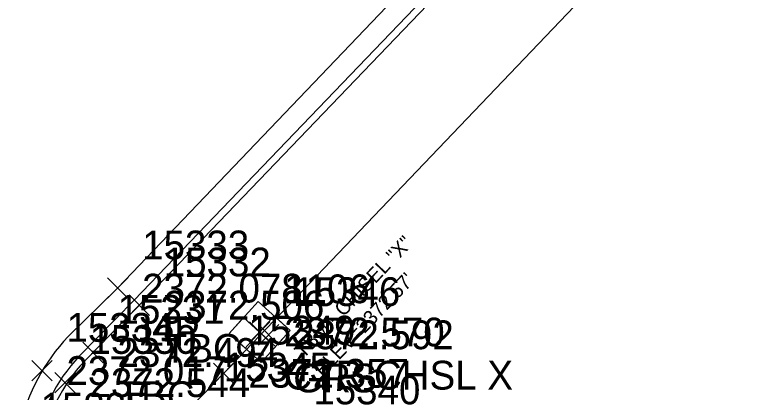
# Model space of a CAD drawing. Extents: x 2377639 to 2379738, y 729875 to 732734.
# Drawn here: x 2378647.8 to 2378700, y 730820.1 to 730846.3 of the extents above; entities that cross this region are included whole.
import ezdxf

# ---------------------------------------------------------------- set-up
doc = ezdxf.new("R2010")
doc.units = 0
for name, color, linetype in [('Default', 7, 'Continuous'), ('SURV_MON_Bench-Mark', 7, 'Continuous'), ('TOPO_CURBGTR_Back-of-Curb', 7, 'Continuous'), ('TOPO_CURBGTR_Face-of-Curb', 7, 'Continuous'), ('TOPO_CURBGTR_Lip-of-Gutter', 7, 'Continuous'), ('TOPO_DATA_Elevations', 7, 'Continuous'), ('TOPO_SW_Back', 7, 'Continuous')]:
    doc.layers.add(name, color=color, linetype=linetype)

# ---------------------------------------------------------------- blocks, each defined once
blk = doc.blocks.new('BM_6')
at = {"layer": 'Default'}
for p, q in [((-0.01905, 0.01905), (-0.01905, -0.01905)), ((0.01905, 0.01905), (-0.01905, 0.01905)), ((0, 0.01905), (0, -0.01905)), ((0.01905, -0.01905), (0.01905, 0.01905)), ((-0.01905, 0), (0.01905, 0)), ((-0.01905, -0.01905), (0.01905, -0.01905))]:
    blk.add_line(p, q, dxfattribs=at)
for points in [[(-0.01905, 0.01905), (0, 0.01905), (0, 0), (-0.01905, 0)], [(-0.01905, 0), (0, 0), (0.01905, 0), (0, 0)], [(0, 0), (0.01905, 0), (0.01905, -0.01905), (0, -0.01905)]]:
    blk.add_lwpolyline(points, close=True, dxfattribs=at)

msp = doc.modelspace()

# ---------------------------------------------------------------- linework, layer by layer
at = {"layer": 'TOPO_CURBGTR_Back-of-Curb'}
msp.add_lwpolyline([(2378652.605, 730822.266), (2378656.409, 730826.165), (2378705.394, 730877.226), (2378739.191, 730912.579), (2378768.062, 730942.704), (2378799.371, 730975.36), (2378801.447, 730977.65), (2378842.099, 731019.831)], dxfattribs=at)
msp.add_arc((2378660.545, 730814.694), 10.972, 136.3589, 206.4791, dxfattribs=at)
at = {"layer": 'TOPO_CURBGTR_Face-of-Curb'}
msp.add_lwpolyline([(2378841.746, 731020.185), (2378801.082, 730977.991), (2378799.005, 730975.701), (2378767.701, 730943.05), (2378738.83, 730912.925), (2378705.033, 730877.572), (2378656.05, 730826.513), (2378652.246, 730822.613)], dxfattribs=at)
msp.add_arc((2378660.545, 730814.694), 11.472, 136.3447, 206.4467, dxfattribs=at)
at = {"layer": 'TOPO_CURBGTR_Lip-of-Gutter'}
msp.add_lwpolyline([(2378651.471, 730823.982), (2378654.908, 730827.348), (2378703.883, 730878.598), (2378754.221, 730930.912), (2378786.673, 730964.807), (2378838.979, 731019.711)], dxfattribs=at)
msp.add_arc((2378661.267, 730814.717), 13.483, 136.5962, 197.493, dxfattribs=at)
at = {"layer": 'TOPO_DATA_Elevations'}
for p, q in [((2378654.201, 730826.641), (2378655.615, 730828.055)), ((2378654.201, 730828.055), (2378655.615, 730826.641)), ((2378655.702, 730825.458), (2378657.116, 730826.872)), ((2378655.702, 730826.872), (2378657.116, 730825.458)), ((2378664.064, 730823.593), (2378665.478, 730825.007)), ((2378664.064, 730825.007), (2378665.478, 730823.593)), ((2378664.694, 730823.397), (2378666.108, 730824.811)), ((2378664.694, 730824.811), (2378666.108, 730823.397)), ((2378652.492, 730822.169), (2378653.906, 730823.583)), ((2378652.492, 730823.583), (2378653.906, 730822.169)), ((2378648.945, 730820.914), (2378650.359, 730822.328)), ((2378648.945, 730822.328), (2378650.359, 730820.914)), ((2378661.58, 730820.723), (2378662.994, 730822.137)), ((2378661.58, 730822.137), (2378662.994, 730820.723)), ((2378650.543, 730820.074), (2378651.957, 730821.488)), ((2378650.543, 730821.488), (2378651.957, 730820.074))]:
    msp.add_line(p, q, dxfattribs=at)
at = {"layer": 'TOPO_SW_Back'}
msp.add_lwpolyline([(2378850.526, 731003.913), (2378844.548, 731009.748), (2378842.486, 731009.625), (2378838.793, 731006.211), (2378801.005, 730966.3), (2378773.557, 730937.716), (2378746.112, 730909.079), (2378732.756, 730895.144), (2378710.995, 730872.441), (2378662.287, 730821.43), (2378657.012, 730815.994), (2378664.569, 730809.005)], dxfattribs=at)

# ---------------------------------------------------------------- block references
at = {"layer": 'SURV_MON_Bench-Mark', "xscale": 78.74000000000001, "yscale": 78.74000000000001, "rotation": 47.89798393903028}
msp.add_blockref('BM_6', (2378664.771, 730824.3), dxfattribs=at)

# ---------------------------------------------------------------- texts
at = {"layer": 'SURV_MON_Bench-Mark'}
for s, p in [('TBM - CHISEL "X"', (2378667.818, 730822.416)), ("ELEV=2372.57'", (2378669.158, 730821.13))]:
    msp.add_text(s, height=1, rotation=46.1837, dxfattribs=at).set_placement(p)
at = {"layer": 'TOPO_DATA_Elevations'}
for s, p in [('15333', (2378656.615, 730829.348)), ('15332', (2378658.116, 730828.165)), ('2372.078', (2378656.615, 730826.348)), ('1106', (2378666.478, 730826.3)), ('15346', (2378667.108, 730826.104)), ('15331', (2378654.906, 730824.876)), ('2372.506', (2378658.116, 730825.165)), ('15334', (2378651.359, 730823.621)), ('LIP', (2378656.615, 730823.348)), ('15349', (2378663.994, 730823.43)), ('2372.570', (2378666.478, 730823.3)), ('15330', (2378652.957, 730822.781)), ('2372.592', (2378667.108, 730823.104)), ('2372.494', (2378654.906, 730821.876)), ('TBC', (2378658.116, 730822.165)), ('15345', (2378662.291, 730820.862)), ('2372.017', (2378651.359, 730820.621)), ('2372.357', (2378663.994, 730820.43)), ('CTR CHSL X', (2378666.478, 730820.3)), ('2372.544', (2378652.957, 730819.781)), ('GRS', (2378667.108, 730820.104)), ('15340', (2378668.507, 730819.275)), ('TBC', (2378654.906, 730818.876)), ('15335', (2378649.56, 730818.08))]:
    msp.add_text(s, height=2, dxfattribs=at).set_placement(p)

doc.saveas('drawing.dxf')
